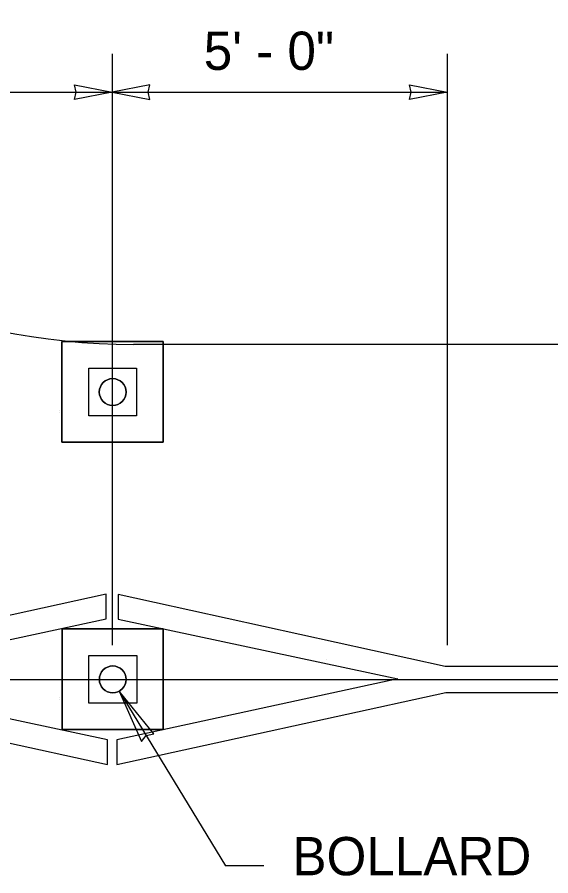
# Model space of a CAD drawing. Extents: x 99862 to 103151, y 100000 to 102076.
# Drawn here: x 100630.8 to 100853.9, y 100379.8 to 100738.5 of the extents above; entities that cross this region are included whole.
import ezdxf

# ---------------------------------------------------------------- set-up
doc = ezdxf.new("R2010")
doc.units = 0
for name, color, linetype in [('Level 1', 7, 'Continuous'), ('Level 15', 7, 'Continuous'), ('Level 2', 7, 'Continuous'), ('Level 20', 7, 'Continuous'), ('Level 22', 7, 'Continuous'), ('Level 3', 7, 'Continuous'), ('Level 8', 7, 'Continuous')]:
    doc.layers.add(name, color=color, linetype=linetype)

msp = doc.modelspace()

# ---------------------------------------------------------------- linework, layer by layer
at = {"layer": 'Level 1'}
for points in [[(100649.56, 100602.98), (100649.56, 100560.94), (100691.88, 100560.94), (100691.88, 100602.98), (100649.56, 100602.98)], [(100660.76, 100571.9), (100660.76, 100591.9), (100680.76, 100591.9), (100680.76, 100571.9), (100660.76, 100571.9)], [(100649.59, 100482.94), (100649.59, 100440.89), (100691.91, 100440.9), (100691.91, 100482.94), (100649.59, 100482.94)], [(100660.79, 100451.85), (100660.79, 100471.85), (100680.79, 100471.85), (100680.79, 100451.85), (100660.79, 100451.85)]]:
    msp.add_lwpolyline(points, dxfattribs=at)
for points in [[(100649.56, 100602.98), (100691.88, 100602.98), (100691.88, 100560.94), (100649.56, 100560.94)], [(100660.76, 100591.9), (100680.76, 100591.9), (100680.76, 100571.9), (100660.76, 100571.9)], [(100649.59, 100482.94), (100691.91, 100482.94), (100691.91, 100440.9), (100649.59, 100440.89)], [(100660.79, 100471.85), (100680.79, 100471.85), (100680.79, 100451.85), (100660.79, 100451.85)]]:
    msp.add_lwpolyline(points, close=True, dxfattribs=at)
for centre in [(100670.76, 100581.9), (100670.76, 100581.9), (100670.79, 100461.85)]:
    msp.add_circle(centre, 5.59, dxfattribs=at)
at = {"layer": 'Level 15'}
for p, q in [((100670.54, 100723.22), (100670.54, 100476.08)), ((100810.54, 100723.22), (100810.54, 100476.08)), ((100530.54, 100707.22), (100670.54, 100707.22)), ((100670.54, 100707.22), (100810.54, 100707.22)), ((100372.08, 100461.81), (101259.58, 100461.81)), ((100673.5, 100456.98), (100717.89, 100383.99)), ((100733.89, 100383.99), (100717.89, 100383.99))]:
    msp.add_line(p, q, dxfattribs=at)
for points in [[(100670.54, 100707.22), (100654.81, 100704.13), (100655.54, 100707.22), (100654.81, 100710.3)], [(100670.54, 100707.22), (100686.26, 100704.13), (100685.54, 100707.22), (100686.26, 100710.3)], [(100810.54, 100707.22), (100794.81, 100704.13), (100795.54, 100707.22), (100794.81, 100710.3)], [(100810.54, 100707.22), (100794.81, 100704.13), (100795.54, 100707.22), (100794.81, 100710.3)], [(100673.5, 100456.98), (100682.81, 100435.93), (100684.81, 100438.38), (100687.91, 100439.03)]]:
    msp.add_lwpolyline(points, close=True, dxfattribs=at)
at = {"layer": 'Level 2'}
for p in [(101252.2, 100601.81), (101251.39, 100601.81)]:
    msp.add_line(p, (100679.47, 100601.81), dxfattribs=at)
msp.add_arc((100679.47, 100881.81), 280, 180, 270, dxfattribs=at)
msp.add_arc((100679.47, 100881.81), 280, 180, 270, dxfattribs=at)
at = {"layer": 'Level 22'}
for p, q in [((100648.54, 100573.45), (100648.54, 100573.45)), ((100648.58, 100574.27), (100648.58, 100574.27)), ((100760.35, 100470.21), (100760.35, 100470.21)), ((100648.57, 100453.41), (100648.57, 100453.41)), ((100648.61, 100454.23), (100648.61, 100454.23)), ((100760.71, 100453.41), (100760.71, 100453.41))]:
    msp.add_line(p, q, dxfattribs=at)
at = {"layer": 'Level 3'}
for centre, start, end in [((100670.76, 100581.9), 0, 180), ((100670.76, 100581.9), 180, 0), ((100670.79, 100461.85), 0, 180), ((100670.79, 100461.85), 180, 0)]:
    msp.add_arc(centre, 5.59, start, end, dxfattribs=at)
at = {"layer": 'Level 8'}
msp.add_lwpolyline([(100550.35, 100461.81), (100667.99, 100487.2), (100667.99, 100497.46), (100530.41, 100467.21), (100399.42, 100467.21), (100399.42, 100456.41), (100530.97, 100456.41), (100668.59, 100426.27), (100668.59, 100436.53)], close=True, dxfattribs=at)
for points in [[(101257.73, 100467.21), (100809.75, 100467.21), (100673.08, 100497.28), (100673.08, 100487.02), (100789.96, 100462.04), (100672.48, 100436.53), (100672.48, 100426.27)], [(100672.48, 100426.27), (100810.1, 100456.41), (101245.67, 100456.41)]]:
    msp.add_lwpolyline(points, dxfattribs=at)

# ---------------------------------------------------------------- texts
at = {"layer": 'Level 20'}
msp.add_text('5\' - 0"', height=16, dxfattribs=at).set_placement((100708.82, 100716.49))
msp.add_text('BOLLARD', height=16, rotation=360, dxfattribs=at).set_placement((100745.89, 100379.99))

doc.saveas('drawing.dxf')
